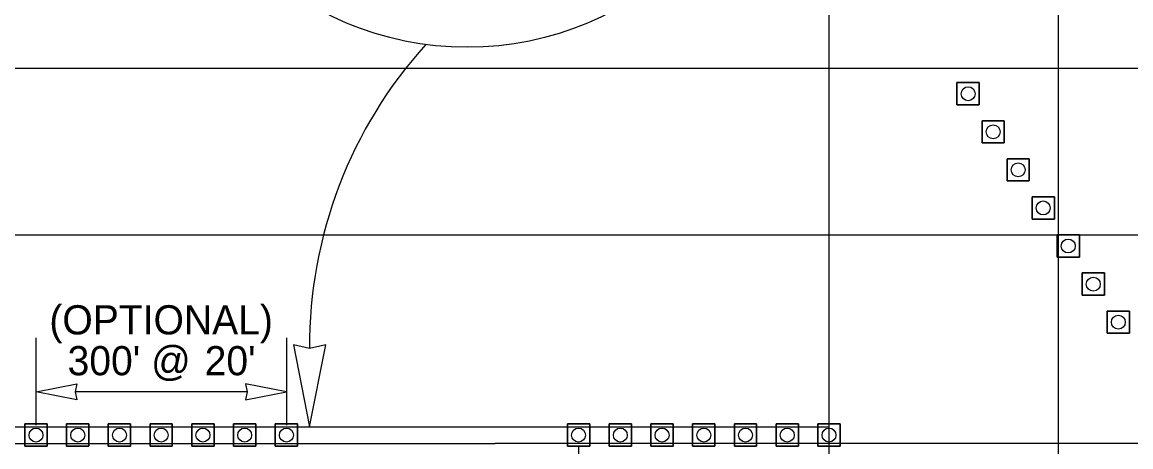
# Model space of a CAD drawing. Extents: x 99999.1 to 100095.7, y 99995 to 100010.7.
# Drawn here: x 100002.344 to 100005, y 100006.584 to 100007.603 of the extents above; entities that cross this region are included whole.
import ezdxf

# ---------------------------------------------------------------- set-up
doc = ezdxf.new("R2010")
doc.units = 0
for name, color, linetype in [('RD_ED_ShoulderPavedEdge', 7, 'Continuous'), ('RD_MK_LineDblYellowCenter', 7, 'Continuous'), ('RD_MK_LineEdgeWhite', 7, 'Continuous'), ('RD_MK_LineNoPass', 7, 'Continuous'), ('RD_MK_LineSkipCenter', 7, 'Continuous'), ('TR_WZ_TrafficCone', 7, 'Continuous'), ('TR_WZ_WorkZoneDetails', 7, 'Continuous'), ('TR_WZ_WorkZoneTextCurrent', 7, 'Continuous')]:
    doc.layers.add(name, color=color, linetype=linetype)

msp = doc.modelspace()

# ---------------------------------------------------------------- linework, layer by layer
at = {"layer": 'RD_ED_ShoulderPavedEdge'}
msp.add_line((100000.1076, 100007.4923), (100015.6424, 100007.4923), dxfattribs=at)
at = {"layer": 'RD_MK_LineDblYellowCenter'}
for p, q in [((100000.1282, 100006.6323), (100003.4767, 100006.6323)), ((100000.0869, 100006.5923), (100003.4767, 100006.5923))]:
    msp.add_line(p, q, dxfattribs=at)
at = {"layer": 'RD_MK_LineEdgeWhite'}
msp.add_line((100000.1076, 100007.0923), (100015.6424, 100007.0923), dxfattribs=at)
at = {"layer": 'RD_MK_LineNoPass'}
msp.add_line((100003.4767, 100006.6323), (100004.2767, 100006.6323), dxfattribs=at)
at = {"layer": 'RD_MK_LineSkipCenter'}
msp.add_lwpolyline([(100011.15, 100006.5923), (100003.4767, 100006.5923)], dxfattribs=at)
at = {"layer": 'TR_WZ_TrafficCone'}
for points in [[(100004.6367, 100007.4577), (100004.5834, 100007.4577), (100004.5834, 100007.4043), (100004.6367, 100007.4043), (100004.6367, 100007.4577)], [(100004.6367, 100007.4043), (100004.5834, 100007.4043), (100004.5834, 100007.4577), (100004.6367, 100007.4577), (100004.6367, 100007.4043)], [(100004.6967, 100007.3663), (100004.6434, 100007.3663), (100004.6434, 100007.313), (100004.6967, 100007.313), (100004.6967, 100007.3663)], [(100004.6967, 100007.313), (100004.6434, 100007.313), (100004.6434, 100007.3663), (100004.6967, 100007.3663), (100004.6967, 100007.313)], [(100004.7567, 100007.275), (100004.7034, 100007.275), (100004.7034, 100007.2217), (100004.7567, 100007.2217), (100004.7567, 100007.275)], [(100004.7567, 100007.2217), (100004.7034, 100007.2217), (100004.7034, 100007.275), (100004.7567, 100007.275), (100004.7567, 100007.2217)], [(100004.8167, 100007.1837), (100004.7634, 100007.1837), (100004.7634, 100007.1303), (100004.8167, 100007.1303), (100004.8167, 100007.1837)], [(100004.8167, 100007.1303), (100004.7634, 100007.1303), (100004.7634, 100007.1837), (100004.8167, 100007.1837), (100004.8167, 100007.1303)], [(100004.8234, 100007.0923), (100004.8767, 100007.0923), (100004.8767, 100007.039), (100004.8234, 100007.039), (100004.8234, 100007.0923)], [(100004.8234, 100007.039), (100004.8767, 100007.039), (100004.8767, 100007.0923), (100004.8234, 100007.0923), (100004.8234, 100007.039)], [(100004.8834, 100007.001), (100004.9367, 100007.001), (100004.9367, 100006.9477), (100004.8834, 100006.9477), (100004.8834, 100007.001)], [(100004.8834, 100006.9477), (100004.9367, 100006.9477), (100004.9367, 100007.001), (100004.8834, 100007.001), (100004.8834, 100006.9477)], [(100004.9434, 100006.9097), (100004.9967, 100006.9097), (100004.9967, 100006.8563), (100004.9434, 100006.8563), (100004.9434, 100006.9097)], [(100004.9434, 100006.8563), (100004.9967, 100006.8563), (100004.9967, 100006.9097), (100004.9434, 100006.9097), (100004.9434, 100006.8563)], [(100002.4033, 100006.639), (100002.35, 100006.639), (100002.35, 100006.5857), (100002.4033, 100006.5857), (100002.4033, 100006.639)], [(100002.4033, 100006.5857), (100002.35, 100006.5857), (100002.35, 100006.639), (100002.4033, 100006.639), (100002.4033, 100006.5857)], [(100002.5033, 100006.639), (100002.45, 100006.639), (100002.45, 100006.5857), (100002.5033, 100006.5857), (100002.5033, 100006.639)], [(100002.5033, 100006.5857), (100002.45, 100006.5857), (100002.45, 100006.639), (100002.5033, 100006.639), (100002.5033, 100006.5857)], [(100002.6033, 100006.639), (100002.55, 100006.639), (100002.55, 100006.5857), (100002.6033, 100006.5857), (100002.6033, 100006.639)], [(100002.6033, 100006.5857), (100002.55, 100006.5857), (100002.55, 100006.639), (100002.6033, 100006.639), (100002.6033, 100006.5857)], [(100002.7033, 100006.639), (100002.65, 100006.639), (100002.65, 100006.5857), (100002.7033, 100006.5857), (100002.7033, 100006.639)], [(100002.7033, 100006.5857), (100002.65, 100006.5857), (100002.65, 100006.639), (100002.7033, 100006.639), (100002.7033, 100006.5857)], [(100002.8033, 100006.639), (100002.75, 100006.639), (100002.75, 100006.5857), (100002.8033, 100006.5857), (100002.8033, 100006.639)], [(100002.8033, 100006.5857), (100002.75, 100006.5857), (100002.75, 100006.639), (100002.8033, 100006.639), (100002.8033, 100006.5857)], [(100002.9033, 100006.639), (100002.85, 100006.639), (100002.85, 100006.5857), (100002.9033, 100006.5857), (100002.9033, 100006.639)], [(100002.9033, 100006.5857), (100002.85, 100006.5857), (100002.85, 100006.639), (100002.9033, 100006.639), (100002.9033, 100006.5857)], [(100003.0033, 100006.639), (100002.95, 100006.639), (100002.95, 100006.5857), (100003.0033, 100006.5857), (100003.0033, 100006.639)], [(100003.0033, 100006.5857), (100002.95, 100006.5857), (100002.95, 100006.639), (100003.0033, 100006.639), (100003.0033, 100006.5857)], [(100003.7033, 100006.639), (100003.65, 100006.639), (100003.65, 100006.5857), (100003.7033, 100006.5857), (100003.7033, 100006.639)], [(100003.7033, 100006.5857), (100003.65, 100006.5857), (100003.65, 100006.639), (100003.7033, 100006.639), (100003.7033, 100006.5857)], [(100003.8033, 100006.639), (100003.75, 100006.639), (100003.75, 100006.5857), (100003.8033, 100006.5857), (100003.8033, 100006.639)], [(100003.8033, 100006.5857), (100003.75, 100006.5857), (100003.75, 100006.639), (100003.8033, 100006.639), (100003.8033, 100006.5857)], [(100003.9033, 100006.639), (100003.85, 100006.639), (100003.85, 100006.5857), (100003.9033, 100006.5857), (100003.9033, 100006.639)], [(100003.9033, 100006.5857), (100003.85, 100006.5857), (100003.85, 100006.639), (100003.9033, 100006.639), (100003.9033, 100006.5857)], [(100004.0033, 100006.639), (100003.95, 100006.639), (100003.95, 100006.5857), (100004.0033, 100006.5857), (100004.0033, 100006.639)], [(100004.0033, 100006.5857), (100003.95, 100006.5857), (100003.95, 100006.639), (100004.0033, 100006.639), (100004.0033, 100006.5857)], [(100004.1033, 100006.639), (100004.05, 100006.639), (100004.05, 100006.5857), (100004.1033, 100006.5857), (100004.1033, 100006.639)], [(100004.1033, 100006.5857), (100004.05, 100006.5857), (100004.05, 100006.639), (100004.1033, 100006.639), (100004.1033, 100006.5857)], [(100004.2033, 100006.639), (100004.15, 100006.639), (100004.15, 100006.5857), (100004.2033, 100006.5857), (100004.2033, 100006.639)], [(100004.2033, 100006.5857), (100004.15, 100006.5857), (100004.15, 100006.639), (100004.2033, 100006.639), (100004.2033, 100006.5857)], [(100004.3033, 100006.639), (100004.25, 100006.639), (100004.25, 100006.5857), (100004.3033, 100006.5857), (100004.3033, 100006.639)], [(100004.3033, 100006.5857), (100004.25, 100006.5857), (100004.25, 100006.639), (100004.3033, 100006.639), (100004.3033, 100006.5857)]]:
    msp.add_lwpolyline(points, dxfattribs=at)
for centre in [(100004.61, 100007.431), (100004.67, 100007.3397), (100004.73, 100007.2483), (100004.79, 100007.157), (100004.85, 100007.0657), (100004.91, 100006.9743), (100004.97, 100006.883), (100002.3767, 100006.6123), (100002.4767, 100006.6123), (100002.5767, 100006.6123), (100002.6767, 100006.6123), (100002.7767, 100006.6123), (100002.8767, 100006.6123), (100002.9767, 100006.6123), (100003.6767, 100006.6123), (100003.7767, 100006.6123), (100003.8767, 100006.6123), (100003.9767, 100006.6123), (100004.0767, 100006.6123), (100004.1767, 100006.6123), (100004.2767, 100006.6123)]:
    msp.add_circle(centre, 0.0167, dxfattribs=at)
at = {"layer": 'TR_WZ_WorkZoneDetails'}
for p, q in [((100004.2767, 100008.7991), (100004.2767, 100005.4923)), ((100004.8267, 100005.4923), (100004.8267, 100007.7323)), ((100002.3767, 100006.6357), (100002.3767, 100006.8457)), ((100002.9767, 100006.8457), (100002.9767, 100006.6357)), ((100002.8829, 100006.7157), (100002.4704, 100006.7157)), ((100003.6767, 100006.5857), (100003.6767, 100006.4023))]:
    msp.add_line(p, q, dxfattribs=at)
for points in [[(100003.0323, 100006.6323), (100003.0708, 100006.8289), (100003.0323, 100006.8198), (100002.9937, 100006.8289)], [(100002.3767, 100006.7157), (100002.4749, 100006.7349), (100002.4704, 100006.7157), (100002.4749, 100006.6964)], [(100002.9767, 100006.7157), (100002.8784, 100006.7349), (100002.8829, 100006.7157), (100002.8784, 100006.6964)]]:
    msp.add_lwpolyline(points, close=True, dxfattribs=at)
msp.add_circle((100003.4096, 100008.2843), 0.742, dxfattribs=at)
msp.add_arc((100004.1081, 100006.8268), 1.0759, 137.8374, 180.3733, dxfattribs=at)

# ---------------------------------------------------------------- texts
at = {"layer": 'TR_WZ_WorkZoneTextCurrent'}
for s, p in [('(OPTIONAL)', (100002.4087, 100006.8537)), ("300' @", (100002.4524, 100006.7557)), ("20'", (100002.7808, 100006.7557))]:
    msp.add_text(s, height=0.07, dxfattribs=at).set_placement(p)

doc.saveas('drawing.dxf')
